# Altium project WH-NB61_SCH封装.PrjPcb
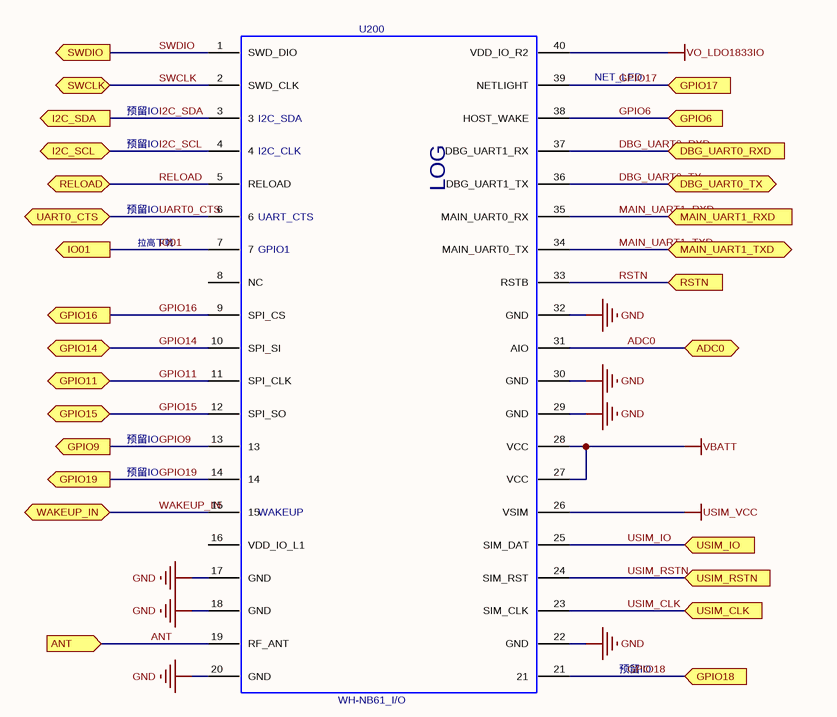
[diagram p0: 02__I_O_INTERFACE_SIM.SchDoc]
1 sheet, 1 parts. Net scope: flat (ports and power ports of the same name join across sheets).

## Sheet 02__I_O_INTERFACE_SIM.SchDoc
size 279 x 215 mm

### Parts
U200  WH-NB61_I/O  [WH-NB61_I/O]

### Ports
ADC0 (bidir), ANT, DBG_UART0_RXD (in), DBG_UART0_TX (bidir), GPIO6 (in), GPIO9 (out), GPIO11 (bidir), GPIO14 (bidir), GPIO15 (bidir), GPIO16 (out), GPIO17 (in), GPIO18 (in), GPIO19 (out), I2C_SCL (bidir), I2C_SDA (out), IO01 (out), MAIN_UART1_RXD (in), MAIN_UART1_TXD (bidir), RELOAD (bidir), RSTN (in), SWCLK (bidir), SWDIO (out), UART0_CTS (bidir), USIM_CLK (in), USIM_IO (in), USIM_RSTN (in), WAKEUP_IN (bidir)

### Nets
GND: U200.17(GND) U200.18(GND) U200.20(GND) U200.22(GND) U200.29(GND) U200.30(GND) U200.32(GND)
USIM_VCC: U200.26(VSIM)
VBATT: U200.27(VCC) U200.28(VCC)
VO_LDO1833IO: U200.40(VDD_IO_R2)
ADC0: U200.31(AIO) ; port ADC0
ANT: U200.19(RF_ANT) ; port ANT
DBG_UART0_RXD: U200.37(DBG_UART1_RX) ; port DBG_UART0_RXD
DBG_UART0_TX: U200.36(DBG_UART1_TX) ; port DBG_UART0_TX
GPIO6: U200.38(HOST_WAKE) ; port GPIO6
GPIO9: U200.13 ; port GPIO9
GPIO11: U200.11(SPI_CLK) ; port GPIO11
GPIO14: U200.10(SPI_SI) ; port GPIO14
GPIO15: U200.12(SPI_SO) ; port GPIO15
GPIO16: U200.9(SPI_CS) ; port GPIO16
GPIO17: U200.39(NETLIGHT) ; port GPIO17
GPIO18: U200.21 ; port GPIO18
GPIO19: U200.14 ; port GPIO19
I2C_SCL: U200.4 ; port I2C_SCL
I2C_SDA: U200.3 ; port I2C_SDA
IO01: U200.7 ; port IO01
MAIN_UART1_RXD: U200.35(MAIN_UART0_RX) ; port MAIN_UART1_RXD
MAIN_UART1_TXD: U200.34(MAIN_UART0_TX) ; port MAIN_UART1_TXD
RELOAD: U200.5(RELOAD) ; port RELOAD
RSTN: U200.33(RSTB) ; port RSTN
SWCLK: U200.2(SWD_CLK) ; port SWCLK
SWDIO: U200.1(SWD_DIO) ; port SWDIO
UART0_CTS: U200.6 ; port UART0_CTS
USIM_CLK: U200.23(SIM_CLK) ; port USIM_CLK
USIM_IO: U200.25(SIM_DAT) ; port USIM_IO
USIM_RSTN: U200.24(SIM_RST) ; port USIM_RSTN
WAKEUP_IN: U200.15 ; port WAKEUP_IN

Not connected (* = marked no-connect by the designer): U200 8(NC) 16(VDD_IO_L1)

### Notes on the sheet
- 预留IO
- (near U200) I2C_SDA
- (near U200) I2C_CLK
- NET_LED
- (near U200) UART_CTS
- (near U200) LOG
- (near U200) 拉高下载
- (near U200) GPIO1
- (near U200) WAKEUP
